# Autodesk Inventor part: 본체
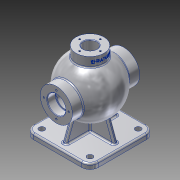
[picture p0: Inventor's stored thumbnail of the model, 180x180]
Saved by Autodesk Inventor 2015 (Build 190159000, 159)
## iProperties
Created: 2025-08
Part Number: 본체
Material: 알루미늄 6061
Document SubType Name: Modeling
Designer: USER
Density: 2.7 g/cm^3
Appearance: 알루미늄 - 평지
Mass: 1525.76 g
Surface Area: 1178.62 cm^2
Volume: 565.097 cm^3
Author: USER
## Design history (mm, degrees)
sketch "스케치2"
  geometry: L1 (-46.5, -62.5)-(46.5, -62.5); L2 (62.5, -46.5)-(62.5, 46.5); L3 (46.5, 62.5)-(-46.5, 62.5); L4 (-62.5, 46.5)-(-62.5, -46.5); L5 (-62.5, -62.5)-(62.5, 62.5); L6 (62.5, -62.5)-(-62.5, 62.5); A1 r 16 centre (-46.5, 46.5) between (-46.5, 62.5) and (-62.5, 46.5); A2 r 16 centre (46.5, 46.5) between (62.5, 46.5) and (46.5, 62.5); A3 r 16 centre (46.5, -46.5) between (46.5, -62.5) and (62.5, -46.5); A4 r 16 centre (-46.5, -46.5) between (-62.5, -46.5) and (-46.5, -62.5); 1 further point
  constraints: 12 end point, 8 point on circle, 8 point on line, 8 tangent, 4 centre point, 3 equal radius, 2 midpoint, 2 parallel, 1 horizontal, 1 perpendicular
  dimensions: "d0" = 125 distance of L6.end L5.end; "d1" = 125 distance of L5.end L6.start; "d4" = 16 radius of A1
extrude "돌출1" new body sketch "스케치2" distance "d2" = 10; taper "d3" = 0 deg
sketch "스케치6"
  geometry: L1 (-46.5, 0)-(46.5, 0) reference; L2 (0, 139)-(0, 31); A1 r 54 centre (0, 85) between (0, 139) and (0, 31); 3 further points
  constraints: 2 end point, 2 midpoint, 2 point on circle, 1 centre point, 1 coincident, 1 vertical, 1 vertical alignment
  dimensions: "d20" = 108 diameter of A1; "d21" = 85 distance from line of A1.centre L1
revolve "회전1" sketch "스케치6" stored, may be unused: angle "d22" = 90 deg
node "작업 평면1"
sketch "스케치7"
  geometry: C1 r 27 at (0, 0); 1 further point
  constraints: 1 centre point, 1 coincident
  dimensions: "d24" = 54 diameter of C1
extrude "돌출2" join sketch "스케치7" stored distance "d25" = 10; taper "d26" = 0 deg
node "작업 평면2"
sketch "스케치8"
  geometry: C1 r 31 at (0, 83); 1 further point
  constraints: 1 centre point, 1 vertical alignment
  dimensions: "d28" = 62 diameter of C1; "d29" = 83 distance of point (0, 0) C1.centre
extrude "돌출3" join sketch "스케치8" distance "d30" = 130; taper "d31" = 0 deg
sketch "스케치9"
  geometry: L1 (-4, -50.5)-(4, -50.5); L2 (4, -50.5)-(4, 50.5); L3 (4, 50.5)-(-4, 50.5); L4 (-4, 50.5)-(-4, -50.5); L5 (-4, -50.5)-(4, 50.5); L6 (4, -50.5)-(-4, 50.5); L7 (-50.5, -4)-(50.5, -4); L8 (50.5, -4)-(50.5, 4); L9 (50.5, 4)-(-50.5, 4); L10 (-50.5, 4)-(-50.5, -4); L11 (-50.5, -4)-(50.5, 4); L12 (50.5, -4)-(-50.5, 4); L13 (-46.5, 62.5)-(46.5, 62.5) reference; L14 (62.5, 46.5)-(62.5, -46.5) reference; 1 further point
  constraints: 24 end point, 4 midpoint, 4 parallel, 2 horizontal, 2 perpendicular
  dimensions: "d32" = 8 distance of L2.end L3.end; "d33" = 8 distance of L7.end L8.end; "d34" = 12 distance between parallel lines of L3 L13; "d35" = 12 distance between parallel lines of L8 L14
extrude "돌출4" join sketch "스케치9" distance "d36" = 85; taper "d37" = 0 deg
feature "면 기울기1" dims angle "d38" = 20 deg
hole "구멍1" diameter "d41" = 26; stored, may be unused: countersink angle "d45" = 90 deg, drill point angle "d47" = 0 deg; dims "d39" = 10, "d40" = 10, "d42" = 6, "d43" = 4, "d44" = 2, "d46" = 100
hole "구멍2" diameter "d50" = 30; stored, may be unused: countersink angle "d54" = 90 deg, drill point angle "d56" = 0 deg; dims "d48" = 10, "d49" = 10, "d51" = 6, "d52" = 35, "d53" = 16, "d55" = 100
sketch "스케치10"
  geometry: L1 (-27, 131.765)-(-27, 150) reference; L2 (-27, 150)-(-13, 150) reference; L3 (-13, 150)-(-13, 98) reference; L4 (-13, 98)-(-49, 98) reference; L5 (-49, 98)-(-49, 100.5) reference; L6 (-49, 100.5)-(-65, 100.5) reference; L7 (-65, 100.5)-(-65, 114) reference; L8 (-65, 114)-(-45.552, 114) reference; L9 (45.552, 114)-(65, 114) reference; L10 (65, 114)-(65, 100.5) reference; L11 (65, 100.5)-(49, 100.5) reference; L12 (49, 100.5)-(49, 98) reference; L13 (49, 98)-(13, 98) reference; L14 (13, 98)-(13, 150) reference; L15 (13, 150)-(27, 150) reference; L16 (27, 150)-(27, 131.765) reference; L17 (-62.5, 0)-(-62.5, 10) reference; L18 (-62.5, 10)-(-50.5, 10) reference; L19 (-50.5, 10)-(-37.385, 46.034) reference; L20 (-42.743, 52)-(-65, 52) reference; L21 (-65, 52)-(-65, 65.5) reference; L22 (-65, 65.5)-(-49, 65.5) reference; L23 (-49, 65.5)-(-49, 68) reference; L24 (-49, 68)-(-13, 68) reference; L25 (-13, 68)-(-13, 50) reference; L26 (-13, 50)-(13, 50) reference; L27 (13, 50)-(13, 68) reference; L28 (13, 68)-(49, 68) reference; L29 (49, 68)-(49, 65.5) reference; L30 (49, 65.5)-(65, 65.5) reference; L31 (65, 65.5)-(65, 52) reference; L32 (65, 52)-(42.743, 52) reference; L33 (37.385, 46.034)-(50.5, 10) reference; L34 (50.5, 10)-(62.5, 10) reference; L35 (62.5, 10)-(62.5, 0) reference; L36 (62.5, 0)-(-62.5, 0) reference; L37 (-44, 85)-(44, 85); L38 (49, 98)-(49, 68) reference; A1 r 54 centre (0, 85) between (-27, 131.765) and (-45.552, 114) reference; A2 r 54 centre (0, 85) between (45.552, 114) and (27, 131.765) reference; A3 r 54 centre (0, 85) between (-42.743, 52) and (-37.385, 46.034) reference; A4 r 54 centre (0, 85) between (37.385, 46.034) and (42.743, 52) reference; A5 r 44 centre (0, 85) between (44, 85) and (-44, 85); 1 further point
  constraints: 2 end point, 2 point on circle, 1 centre point, 1 coincident, 1 midpoint, 1 perpendicular
  dimensions: "d57" = 88 diameter of A5
revolve "회전2" sketch "스케치10" stored, may be unused: angle "d58" = 90 deg
sketch "스케치11"
  geometry: 1 further point
sketch "스케치12"
  geometry: L1 (0, 0)-(20, 0)
  constraints: 2 end point, 1 horizontal
  dimensions: "d59" = 20 distance of L1.start L1.end
hole "구멍3" sketch "스케치12" at (20, 0) diameter "d60" = 3.242; stored, may be unused: countersink angle "d64" = 90 deg, drill point angle "d66" = 118 deg; dims "d61" = 12, "d62" = 35, "d63" = 16, "d65" = 15
sketch "스케치13"
  geometry: L1 (0, 0)-(0, 24); C1 r 17.5 at (0, 0) reference; C2 r 31 at (0, 0) reference; 1 further point
  constraints: 2 end point, 1 vertical
  dimensions: "d70" = 24 distance of L1.start L1.end
hole "구멍4" sketch "스케치13" at (0, 24) diameter "d71" = 3.242; stored, may be unused: countersink angle "d75" = 90 deg, drill point angle "d77" = 118 deg; dims "d72" = 12, "d73" = 35, "d74" = 16, "d76" = 15
sketch "스케치14"
  geometry: 1 further point
sketch "스케치15"
  geometry: L1 (-13, 150)-(13, 150) reference; 3 further points
  constraints: 1 midpoint, 1 vertical alignment, 1 other
  dimensions: "d81" = 9 distance from line of point (0, 141) L1
feature "엠보싱1" sketch "스케치15" dims "d0" = 125, "d1" = 125, "d4" = 16, "d20" = 108, "d21" = 85, "d82" = 0.5, "d83" = 0
chamfer "모따기1" distance "d84" = 1; stored, may be unused: second distance "d85" = 2, angle "d86" = 45 deg
fillet "모깎기1" dims "d87" = 0.6
fillet "모깎기2" dims "d88" = 3
fillet "모깎기3" dims "d89" = 3
fillet "모깎기4" dims "d90" = 3
hole "구멍5" diameter "d93" = 11; stored, may be unused: countersink angle "d97" = 90 deg, drill point angle "d99" = 0 deg; dims "d91" = 10, "d92" = 10, "d94" = 12, "d95" = 35, "d96" = 16, "d98" = 15
node "솔리드1"
mirror "대칭1"
pattern_circular "원형 패턴1" dims angle "d68" = 360 deg
pattern_circular "원형 패턴2" dims angle "d79" = 360 deg
mirror "대칭2"
pattern_linear "직사각형 패턴1" dims "d102" = 93, "d105" = 93
node "투영된 루프1"
node "절단 모서리 투영2"
other parameters: "d27" = -65
